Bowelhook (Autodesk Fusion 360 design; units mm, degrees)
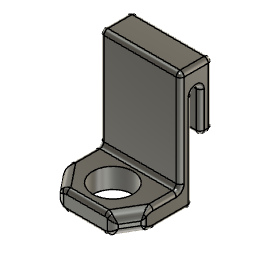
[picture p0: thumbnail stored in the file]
box_primitive "BoxPrimitive1" DistanceX 17 DistanceY 20 DistanceZ 5 OffsetDistanceX 0 OffsetDistanceY 0
hole "Hole1" HoleDepth 10 HoleDiameter 10 TipAngle 180
box_primitive "BoxPrimitive2" DistanceX 3 DistanceY 20 DistanceZ 25 OffsetDistanceX 0 OffsetDistanceY 0
box_primitive "BoxPrimitive3" DistanceX 5 DistanceY 20 DistanceZ 5 OffsetDistanceX 0 OffsetDistanceY 0
box_primitive "BoxPrimitive4" DistanceX 3 DistanceY 20 DistanceZ 11 OffsetDistanceX 0 OffsetDistanceY 0
fillet "Fillet1" radius 1
fillet "Fillet2" radius 1 1
fillet "Fillet3" radius 1 1
sketch "Sketch16" plane through (0, 0, 5) normal (0, 0, 1) x axis (-1, 0, 0)
  line L1 (-19, -4) -> (-1, -4)
  line L2 (-19, -16) -> (-19, -4)
  line L3 (-1, -16) -> (-19, -16)
  line L4 (-1, -4) -> (-1, -16)
  line L5 (-4, -3) -> (0, -8)
  line L6 (0, -1) -> (-4, -3)
  line L7 (0, -8) -> (0, -1)
  line L8 (-17, -3) -> (-20, -8)
  line L9 (-20, -2) -> (-17, -3)
  line L10 (-21.6311, -6.8932) -> (-20, -2)
  line L11 (-20, -8) -> (-21.6311, -6.8932)
  line L12 (0, -2) -> (0, -1)
  circle C1 centre (-9.9296, -10.297) radius 5
  point P14 (0, -2)
  parallel L4 L7
  perpendicular L9 L10
  coincident L7 P14
extrude "Extrude1" cut sketch "Sketch16" profile of L1 L2 L4 L5 L6 L7 L8 L9 L10 L11 L12 against normal blind 8
fillet "Fillet4" radius 2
